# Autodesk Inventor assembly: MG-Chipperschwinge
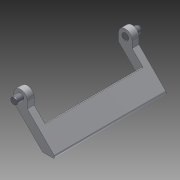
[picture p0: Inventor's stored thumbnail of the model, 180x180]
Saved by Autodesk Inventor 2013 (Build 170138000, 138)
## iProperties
Created: 2012-07
Part Number: MG-Chipperschwinge
Document SubType Name: Assembly
Designer: rYan
Mass: 15.3256 g
Surface Area: 39.8933 cm^2
Volume: 5.27879 cm^3
Density: 2.90325 g/cm^3
Author: rYan
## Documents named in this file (3)
- D:\SVN\2013\Inventor\Kicker\Chip\MG-Chipperschwinge.iam
- D:\SVN\2013\Inventor\Kaufteile\ISO 8734 - 4 x 8 - ADIN EN.ipt
- D:\SVN\2013\Inventor\Kicker\Chip\Chipperschwinge.ipt
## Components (3 placed, 2 different names)
1. Chipperschwinge:1 — Passend:1, Passend:2, Fluchtend:1, Fluchtend:2
2. ISO 8734 - 4 x 8 - ADIN EN:1 — Passend:1, Fluchtend:1
3. ISO 8734 - 4 x 8 - ADIN EN:2 — Passend:2, Fluchtend:2
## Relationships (4: Mate 2, Flush 2)
- Passend:1 [Mate]: Chipperschwinge:1 ↔ ISO 8734 - 4 x 8 - ADIN EN:1
- Passend:2 [Mate]: Chipperschwinge:1 ↔ ISO 8734 - 4 x 8 - ADIN EN:2
- Fluchtend:1 [Flush]: Chipperschwinge:1 ↔ ISO 8734 - 4 x 8 - ADIN EN:1
- Fluchtend:2 [Flush]: Chipperschwinge:1 ↔ ISO 8734 - 4 x 8 - ADIN EN:2
